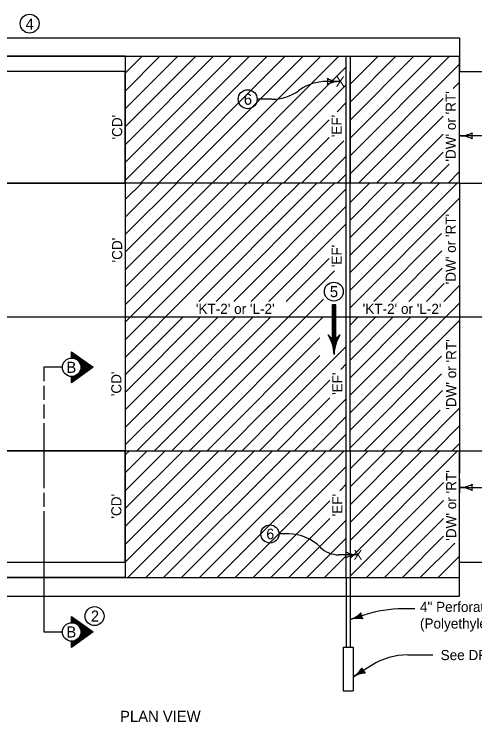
# Model space of a CAD drawing. Extents: x 10045 to 81668, y 6370 to 11018.
# Drawn here: x 22073 to 22837, y 6425 to 7599 of the extents above; entities that cross this region are included whole.
import ezdxf

# ---------------------------------------------------------------- set-up
doc = ezdxf.new("R2010")
doc.units = 0
for name, color, linetype in [('Alignment', 7, 'Continuous'), ('Default', 7, 'Continuous'), ('dsnStdLineWork', 7, 'Continuous')]:
    doc.layers.add(name, color=color, linetype=linetype)

msp = doc.modelspace()

# ---------------------------------------------------------------- linework, layer by layer
at = {"layer": 'Alignment'}
for p, q in [((22811.9, 7366), (22811.9, 7407.4)), ((22956.4, 7397.2), (22811.9, 7397.2)), ((22811.9, 7318.7), (22811.9, 6874.6)), ((22616.6, 6895.1), (22623.8, 6902.3)), ((21447.5, 6874.6), (22811.9, 6874.6)), ((22811.9, 6828), (22811.9, 6804.1)), ((22811.9, 6813.7), (22955.5, 6813.7)), ((22121.6, 6774.1), (22121.6, 6573.9)), ((22528.3, 6736.5), (22512, 6736.5)), ((22642.8, 6701.9), (22611.6, 6701.9)), ((22737.3, 6612.2), (22717.6, 6612.2)), ((22767.3, 6535.6), (22725.8, 6535.6)), ((22665.7, 6518.4), (22635.1, 6499.2))]:
    msp.add_line(p, q, dxfattribs=at)
for points in [[(22152.5, 7013.1), (22121.6, 7013.1), (22121.6, 6990)], [(22121.6, 6982.3), (22121.6, 6959.2)], [(22121.6, 6951.5), (22121.6, 6928.3)], [(22121.6, 6920.6), (22121.6, 6812.7)], [(22121.6, 6805), (22121.6, 6781.8)], [(22121.6, 6585.3), (22121.6, 6573.9), (22152.5, 6573.9)]]:
    msp.add_lwpolyline(points, dxfattribs=at)
for centre, radius, start, end in [((22528.3, 6663.1), 73.4, 45, 90), ((22611.6, 6746), 44.1, 225, 270), ((22717.6, 6406.6), 205.6, 90, 107.8594), ((22725.8, 6422.6), 113.1, 90, 122.0832)]:
    msp.add_arc(centre, radius, start, end, dxfattribs=at)
at = {"layer": 'Default'}
msp.add_line((21886.8, 7529.2), (22811.9, 7529.2), dxfattribs=at)
at = {"layer": 'dsnStdLineWork'}
for p, q in [((21923.8, 7560), (22811.9, 7560)), ((22811.9, 7560), (22811.9, 7503.7)), ((21886.8, 7529.2), (22256.8, 7529.2)), ((22256.8, 7529.2), (21886.8, 7529.2)), ((22256.8, 7529.2), (22256.8, 6874.6)), ((22256.8, 7323), (22463, 7529.2)), ((22256.8, 7352.7), (22433.3, 7529.2)), ((22256.8, 7382.4), (22403.6, 7529.2)), ((22256.8, 7412.1), (22373.9, 7529.2)), ((22256.8, 7441.8), (22344.2, 7529.2)), ((22256.8, 7471.5), (22314.5, 7529.2)), ((22256.8, 7501.2), (22284.8, 7529.2)), ((22282.2, 7318.7), (22492.7, 7529.2)), ((22311.9, 7318.7), (22522.4, 7529.2)), ((22341.6, 7318.7), (22552.1, 7529.2)), ((22371.3, 7318.7), (22581.8, 7529.2)), ((22401, 7318.7), (22611.5, 7529.2)), ((22623.8, 7318.7), (22623.8, 7529.2)), ((22630, 7529.2), (22630, 7318.7)), ((22630, 7363.9), (22795.3, 7529.2)), ((22630, 7393.6), (22765.6, 7529.2)), ((22630, 7423.3), (22735.9, 7529.2)), ((22630, 7453), (22706.2, 7529.2)), ((22630, 7482.7), (22676.5, 7529.2)), ((22811.9, 7318.7), (22811.9, 7529.2)), ((22630, 7334.2), (22811.9, 7516.1)), ((22430.7, 7318.7), (22623.8, 7511.8)), ((22256.9, 7503.7), (21886.8, 7503.7)), ((22256.8, 7318.7), (22256.8, 7503.7)), ((22256.9, 7318.7), (22256.9, 7503.7)), ((22623.8, 7318.7), (22623.8, 7503.7)), ((22630, 7318.7), (22630, 7503.7)), ((22811.9, 7503.7), (23322.7, 7503.7)), ((22811.9, 7318.7), (22811.9, 7503.7)), ((22460.4, 7318.7), (22623.8, 7482.1)), ((22613.5, 7487.4), (22590.8, 7487.4)), ((22801.3, 7475.8), (22811.9, 7486.4)), ((22546.6, 7473.4), (22544.3, 7471.8)), ((22500.1, 7457.9), (22475.9, 7457.9)), ((22644.2, 7318.7), (22784.8, 7459.3)), ((22608.6, 7437.2), (22623.8, 7452.4)), ((22490.1, 7318.7), (22595.4, 7424)), ((22673.9, 7318.7), (22784.8, 7429.6)), ((22703.6, 7318.7), (22784.8, 7399.9)), ((22519.8, 7318.7), (22595.4, 7394.3)), ((22549.5, 7318.7), (22619.8, 7389)), ((22733.3, 7318.7), (22784.8, 7370.2)), ((22579.2, 7318.7), (22623.8, 7363.3)), ((22811.9, 7318.7), (22811.9, 7355.7)), ((22763, 7318.7), (22794.7, 7350.4)), ((22608.9, 7318.7), (22623.8, 7333.6)), ((22792.7, 7318.7), (22811.9, 7337.9)), ((22811.9, 7318.7), (21400.9, 7318.7)), ((21886.8, 7318.7), (22256.9, 7318.7)), ((21886.8, 7318.7), (22256.9, 7318.7)), ((22256.8, 7291.3), (22284.2, 7318.7)), ((22256.8, 7262.2), (22313.3, 7318.7)), ((22256.8, 7233.2), (22342.4, 7318.7)), ((22256.8, 7204.1), (22371.4, 7318.7)), ((22256.8, 7175), (22400.5, 7318.7)), ((22256.8, 7145.9), (22429.6, 7318.7)), ((22256.8, 7116.9), (22458.7, 7318.7)), ((22256.9, 7318.7), (22256.9, 6874.6)), ((22461.5, 7292.4), (22487.7, 7318.7)), ((22478.9, 7280.7), (22516.8, 7318.7)), ((22504.8, 7277.6), (22545.9, 7318.7)), ((22553.2, 7296.9), (22575, 7318.7)), ((22595.5, 7310.2), (22604, 7318.7)), ((22623.8, 6874.6), (22623.8, 7318.7)), ((22630, 6874.6), (22630, 7318.7)), ((22630, 7286.5), (22662.2, 7318.7)), ((22630, 7257.4), (22691.3, 7318.7)), ((22630, 7228.3), (22720.3, 7318.7)), ((22630, 7141.1), (22807.6, 7318.7)), ((22630, 7199.3), (22749.4, 7318.7)), ((22630, 7170.2), (22778.5, 7318.7)), ((22811.9, 7318.7), (23357.5, 7318.7)), ((22407.8, 7122.5), (22595.5, 7310.2)), ((22436.9, 7122.5), (22623.8, 7309.4)), ((22378.8, 7122.5), (22553.2, 7296.9)), ((22630, 7112), (22811.9, 7294)), ((22256.8, 7087.8), (22461.5, 7292.4)), ((22256.8, 7058.7), (22478.9, 7280.7)), ((22370.4, 7143.2), (22504.8, 7277.6)), ((22466, 7122.5), (22623.8, 7280.3)), ((22504.8, 7277.6), (22497.9, 7270.8)), ((22495.1, 7122.5), (22623.8, 7251.2)), ((22669.5, 7122.5), (22782, 7235)), ((22256.4, 7208.8), (22256.8, 7209.2)), ((22698.6, 7122.5), (22782.2, 7206.2)), ((22524.1, 7122.5), (22595.4, 7193.7)), ((22727.7, 7122.5), (22782.7, 7177.5)), ((22305.3, 6874.6), (22604, 7173.3)), ((22756.7, 7122.5), (22786.3, 7152.1)), ((22256.8, 7029.6), (22370.4, 7143.2)), ((22785.8, 7122.5), (22811.9, 7148.6)), ((22334.4, 6874.6), (22586, 7126.3)), ((22630, 6937.6), (22811.9, 7119.5)), ((22603.4, 7062), (22603.4, 7116.5)), ((21886.8, 7096.7), (23403.1, 7096.7)), ((22256.8, 7000.6), (22352.9, 7096.7)), ((22256.8, 6971.5), (22382, 7096.7)), ((22256.8, 6942.4), (22411.1, 7096.7)), ((22256.8, 6913.3), (22440.1, 7096.7)), ((22331.2, 6958.6), (22469.2, 7096.7)), ((22345.7, 6944), (22498.3, 7096.7)), ((22363.5, 6874.6), (22585.5, 7096.7)), ((22630, 6995.7), (22730.9, 7096.7)), ((22630, 7024.8), (22701.8, 7096.7)), ((22630, 6966.7), (22760, 7096.7)), ((22630, 7053.9), (22672.7, 7096.7)), ((22630, 7083), (22643.7, 7096.7)), ((22630, 6908.5), (22811.9, 7090.5)), ((22392.6, 6874.6), (22580.1, 7062.1)), ((22600.3, 7062.1), (22600.3, 7062.1)), ((22606.7, 7062.1), (22606.7, 7062.1)), ((22509, 6932.9), (22623.8, 7047.7)), ((22492.5, 6945.5), (22579.7, 7032.6)), ((22630, 6879.4), (22782, 7031.4)), ((22614.7, 7009.6), (22623.8, 7018.6)), ((22654.2, 6874.6), (22781.7, 7002.1)), ((22537.5, 6932.3), (22596.6, 6991.5)), ((22683.3, 6874.6), (22783.4, 6974.7)), ((22256.8, 6884.3), (22331.2, 6958.6)), ((22560, 6925.7), (22596.6, 6962.4)), ((22576.4, 6913.1), (22623.8, 6960.5)), ((22276.3, 6874.6), (22345.7, 6944)), ((22421.6, 6874.6), (22496.6, 6949.6)), ((22712.4, 6874.6), (22779.8, 6942)), ((22741.5, 6874.6), (22811.9, 6945.1)), ((22450.7, 6874.6), (22509, 6932.9)), ((22479.8, 6874.6), (22537.5, 6932.3)), ((22508.9, 6874.6), (22564.4, 6930.1)), ((22591.9, 6899.5), (22623.8, 6931.4)), ((22537.9, 6874.6), (22579.5, 6916.2)), ((22770.5, 6874.6), (22811.9, 6916)), ((22567, 6874.6), (22591.9, 6899.5)), ((22596.1, 6874.6), (22616.6, 6895.1)), ((22799.6, 6874.6), (22811.9, 6886.9)), ((22256.9, 6874.6), (21886.8, 6874.6)), ((22256.9, 6874.6), (21886.8, 6874.6)), ((22256.8, 6874.6), (22256.8, 6689.6)), ((22256.8, 6874.6), (22256.8, 6689.6)), ((22256.8, 6874.6), (22256.8, 6664.1)), ((22256.8, 6719.2), (22412.2, 6874.6)), ((22256.8, 6748.9), (22382.5, 6874.6)), ((22256.8, 6808.3), (22323.1, 6874.6)), ((22256.8, 6838), (22293.4, 6874.6)), ((22256.8, 6867.7), (22263.7, 6874.6)), ((22256.8, 6778.6), (22352.8, 6874.6)), ((22256.9, 6689.6), (22441.9, 6874.6)), ((22256.9, 6689.6), (22256.9, 6874.6)), ((22261.2, 6664.1), (22471.6, 6874.6)), ((22290.9, 6664.1), (22501.3, 6874.6)), ((22320.6, 6664.1), (22531, 6874.6)), ((22350.3, 6664.1), (22560.7, 6874.6)), ((22379.9, 6664.1), (22590.4, 6874.6)), ((22409.6, 6664.1), (22620.1, 6874.6)), ((22623.8, 6664.1), (22623.8, 6874.6)), ((22630, 6874.6), (22630, 6664.1)), ((22630, 6696), (22808.6, 6874.6)), ((22630, 6725.7), (22778.9, 6874.6)), ((22630, 6755.4), (22749.2, 6874.6)), ((22630, 6785.1), (22719.5, 6874.6)), ((22630, 6814.8), (22689.8, 6874.6)), ((22630, 6844.5), (22660.1, 6874.6)), ((22630, 6874.2), (22630.4, 6874.6)), ((22811.9, 6874.6), (22811.9, 6837.6)), ((22811.9, 6874.6), (23357.5, 6874.6)), ((22811.9, 6689.6), (22811.9, 6874.6)), ((22811.9, 6664.1), (22811.9, 6874.6)), ((22439.3, 6664.1), (22623.8, 6848.6)), ((22613, 6808.1), (22623.8, 6818.9)), ((22630, 6666.3), (22785.4, 6821.8)), ((22469, 6664.1), (22596.6, 6791.7)), ((22657.5, 6664.1), (22785.4, 6792.1)), ((22498.7, 6664.1), (22596.6, 6762)), ((22528.4, 6664.1), (22623.8, 6759.5)), ((22687.2, 6664.1), (22785.4, 6762.4)), ((22558.1, 6664.1), (22623.8, 6729.8)), ((22716.9, 6664.1), (22785.4, 6732.7)), ((22746.6, 6664.1), (22803.8, 6721.3)), ((22587.8, 6664.1), (22623.8, 6700.1)), ((22776.3, 6664.1), (22811.9, 6699.8)), ((21886.8, 6689.6), (22256.9, 6689.6)), ((22811.9, 6689.6), (23322.7, 6689.6)), ((22811.9, 6633.3), (22811.9, 6689.6)), ((21886.8, 6664.1), (22811.9, 6664.1)), ((22623.8, 6664.1), (22623.8, 6548.4)), ((22630, 6664.1), (22630, 6548.4)), ((21923.8, 6633.3), (22811.9, 6633.3)), ((22654.6, 6602.3), (22630, 6594.4)), ((22630, 6594.4), (22648.8, 6600.5)), ((22618.7, 6548.4), (22635.1, 6548.4)), ((22618.7, 6548.4), (22618.7, 6476)), ((22635.1, 6548.4), (22635.1, 6476)), ((22635.1, 6499.2), (22651.9, 6509.7)), ((22618.7, 6476), (22635.1, 6476))]:
    msp.add_line(p, q, dxfattribs=at)
for points in [[(21886.8, 7511.4), (21886.8, 7511.4), (21886.8, 7529.2), (22256.8, 7529.2), (22256.8, 7503.7), (21886.8, 7503.7)], [(21886.8, 6681.9), (21886.8, 6689.6), (22256.8, 6689.6), (22256.8, 6664.1), (21886.8, 6664.1), (21886.8, 6681.9)]]:
    msp.add_lwpolyline(points, close=True, dxfattribs=at)
for points in [[(22623.8, 7318.7), (22623.8, 7318.7)], [(22630, 7318.7), (22630, 7318.7)], [(22606.5, 7062.1), (22606.5, 7116.5), (22600.3, 7116.5), (22600.3, 7062.1), (22605.6, 7062.2), (22605.8, 7115.8), (22600.9, 7115.7), (22601.1, 7063.3), (22604.8, 7063.1), (22605, 7115), (22601.7, 7114.9), (22601.7, 7063.9), (22604.1, 7063.8), (22604.3, 7114.4), (22602.5, 7114.4), (22602.6, 7064.6)], [(22610.5, 7063.5), (22606.8, 7061.2), (22601.5, 7061), (22596.8, 7062.9), (22600.1, 7054.9), (22602.8, 7045.5), (22603.4, 7042.8), (22604.8, 7049.6), (22608.2, 7059.5), (22609.8, 7062.5), (22598.3, 7061.4), (22603.2, 7046.9), (22607.5, 7061), (22599.6, 7060.5), (22603.3, 7050.5), (22605.5, 7059.7), (22601, 7060.1), (22603, 7053.7), (22604.4, 7058.6), (22602.2, 7058.8), (22602.9, 7056.5)], [(22167.9, 7028.5), (22167.9, 7038.8), (22203.9, 7013.1), (22167.9, 6987.4), (22167.9, 6997.7)], [(22168.9, 6996.7), (22168.8, 6989.3), (22201.9, 7013.1), (22168.7, 7037.2), (22169, 7029.3), (22170.4, 7028.9), (22169.8, 7034.6), (22199.8, 7013.1), (22169.8, 6991.3), (22170.1, 6996.9), (22171.2, 6997.1), (22171.1, 6993.4), (22197.7, 7013.2), (22171.1, 7032), (22171.6, 7028.8), (22172.8, 7028.5), (22172.6, 7029.6), (22195.5, 7012.9), (22172.2, 6995.4), (22173.4, 6997.3), (22193.5, 7012.7), (22181.2, 7022.5), (22181.9, 7020.7), (22191.4, 7012.7), (22182.2, 7005.7), (22183.1, 7007.6), (22189.4, 7012.4), (22183.1, 7017.9), (22183.7, 7015.5), (22187.8, 7012.4), (22183.6, 7009.1), (22183.9, 7010.8), (22186.3, 7012.3), (22183.9, 7013.7), (22184.1, 7012.2), (22184.9, 7012.3)], [(22623.8, 6874.6), (22623.8, 6874.6)], [(22649.5, 6596.9), (22647.7, 6600.1), (22647.3, 6603.9), (22643.7, 6600.5), (22637.5, 6596.9), (22645.3, 6597.5), (22648.8, 6597.1), (22647, 6599.9), (22646.6, 6602.3), (22644.3, 6600.1), (22640.9, 6597.9), (22645.2, 6598.1), (22647.5, 6598), (22646.1, 6600.9), (22643.8, 6598.9), (22646.1, 6598.9), (22645.8, 6599.9), (22644.9, 6599.3)], [(22167.9, 6589.3), (22167.9, 6599.6), (22203.9, 6573.9), (22167.9, 6548.2), (22167.9, 6558.5)], [(22168.9, 6557.5), (22168.8, 6550), (22201.9, 6573.9), (22168.7, 6598), (22169, 6590.1), (22170.4, 6589.7), (22169.8, 6595.4), (22199.8, 6573.9), (22169.8, 6552.1), (22170.1, 6557.6), (22171.2, 6557.9), (22171.1, 6554.2), (22197.7, 6574), (22171.1, 6592.8), (22171.6, 6589.6), (22172.8, 6589.3), (22172.6, 6590.4), (22195.5, 6573.7), (22172.2, 6556.2), (22173.4, 6558.1), (22193.5, 6573.5), (22181.2, 6583.3), (22181.9, 6581.5), (22191.4, 6573.5), (22182.2, 6566.5), (22183.1, 6568.3), (22189.4, 6573.2), (22183.1, 6578.7), (22183.7, 6576.3), (22187.8, 6573.2), (22183.6, 6569.9), (22183.9, 6571.6), (22186.3, 6573.1), (22183.9, 6574.5), (22184.1, 6573), (22184.9, 6573.1)], [(22653.5, 6506.4), (22650.9, 6509.1), (22649.6, 6512.6), (22647, 6508.5), (22641.8, 6503.4), (22649.2, 6506), (22652.7, 6506.4), (22650.3, 6508.7), (22649.3, 6510.9), (22647.6, 6508.2), (22644.8, 6505.3), (22649, 6506.5), (22651.2, 6507), (22649.2, 6509.4), (22647.4, 6506.9), (22649.7, 6507.5), (22649.1, 6508.4), (22648.4, 6507.6)]]:
    msp.add_lwpolyline(points, dxfattribs=at)
for centre, radius in [((22098.2, 7583.4), 15.7), ((22460.1, 7457.9), 15.7), ((22603.1, 7138.7), 15.7), ((22167.9, 7013.1), 15.4), ((22497, 6736.5), 15), ((22206, 6600.2), 15.7), ((22167.9, 6573.9), 15.4)]:
    msp.add_circle(centre, radius, dxfattribs=at)
for centre, radius, start, end in [((22576.3, 7487.4), 17.1, 342.2666, 17.7334), ((22613.5, 7531.8), 44.4, 241.9275, 270), ((22576.3, 7487.4), 17.1, 342.2666, 17.7334), ((22613.5, 7531.8), 44.4, 241.9275, 270), ((22590.8, 7410.3), 77.1, 90, 124.9993), ((22613.5, 7443), 44.4, 90, 118.0725), ((22613.5, 7443), 44.4, 90, 118.0725), ((22500.1, 7535), 77.1, 270, 304.9999), ((22811.9, 7441.5), 44.4, 270, 298.0725), ((22849.1, 7397.2), 17.1, 162.2666, 197.7334), ((22811.9, 7352.8), 44.4, 61.9275, 90), ((22603.4, 7073.3), 11.6, 211.7147, 328.2853), ((22537.2, 7032.3), 66.3, 1.6842, 31.7143), ((22669.7, 7032.3), 66.3, 148.2857, 178.3158), ((22811.9, 6858.3), 44.6, 270, 298.0725), ((22811.9, 6858.3), 44.6, 270, 298.0725), ((22811.9, 6769.1), 44.6, 61.9275, 90), ((22811.9, 6769.1), 44.6, 61.9275, 90), ((22849.3, 6813.7), 17.2, 162.2666, 197.7334), ((22849.3, 6813.7), 17.2, 162.2666, 197.7334), ((22607.4, 6701.9), 16.3, 342.2666, 17.7333), ((22642.8, 6744.2), 42.3, 241.9275, 270), ((22642.8, 6659.6), 42.3, 90, 118.0725), ((22616.6, 6636), 43.7, 287.8585, 315.9309), ((22664.8, 6605.6), 16.9, 180.1251, 215.5918), ((22643.4, 6552.8), 43.7, 79.786, 107.8585), ((22611.9, 6536.2), 43.7, 302.0841, 330.1566), ((22666.2, 6518.7), 16.9, 194.3508, 229.8175), ((22658.3, 6462.2), 43.7, 94.0116, 122.0841)]:
    msp.add_arc(centre, radius, start, end, dxfattribs=at)

# ---------------------------------------------------------------- texts
at = {"layer": 'Alignment'}
for s, height, p in [('4', 18.4, (22091.4, 7573.5)), ('X', 16.8, (22606.4, 7479)), ('6', 18.4, (22453.7, 7448.7)), ('5', 18.4, (22596.5, 7129.5)), ("'KT-2' or 'L-2'", 16.8, (22374.1, 7101.7)), ("'KT-2' or 'L-2'", 16.8, (22651, 7101.7)), ('B', 18.4, (22159.2, 7003.9)), ('6', 17.5, (22491.1, 6727.8)), ('X', 16, (22636, 6693.9)), ('4" Perforated Subdrain ', 16.8, (22746.1, 6607.1)), ('2', 18.4, (22199.8, 6591)), ('(Polyethylene, Corrugated Tubing)', 16.8, (22746.1, 6579.6)), ('B', 18.4, (22159.2, 6564.7)), ('See DR-306 for outlet details', 16.8, (22780.4, 6527.2)), ('PLAN VIEW', 18.37, (22248.3, 6424.7))]:
    msp.add_text(s, height=height, dxfattribs=at).set_placement(p)
for s, p in [("'DW' or 'RT'", (22805.6, 7354.4)), ("'CD'", (22251.8, 7391.1)), ("'EF'", (22616.2, 7394.9)), ("'DW' or 'RT'", (22805.6, 7150.8)), ("'CD'", (22251.8, 7187.1)), ("'EF'", (22616.2, 7179.2)), ("'DW' or 'RT'", (22806.2, 6942.6)), ("'CD'", (22250.5, 6965.1)), ("'EF'", (22617.4, 6967.3)), ("'DW' or 'RT'", (22806.2, 6725.3)), ("'CD'", (22250.5, 6762)), ("'EF'", (22617.4, 6765.8))]:
    msp.add_text(s, height=16.8, rotation=90, dxfattribs=at).set_placement(p)

doc.saveas('drawing.dxf')
